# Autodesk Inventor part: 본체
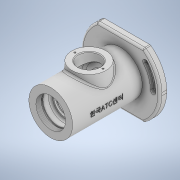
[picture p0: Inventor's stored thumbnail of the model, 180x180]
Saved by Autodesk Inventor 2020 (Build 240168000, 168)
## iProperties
Created: 2022-05
Part Number: 본체
Material: 일반
Document SubType Name: Modeling
Designer: Student
Density: 1 g/cm^3
Appearance: 기본값
Mass: 253.813 g
Surface Area: 621.423 cm^2
Volume: 253.813 cm^3
Author: Student
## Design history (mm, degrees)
sketch "스케치1"
  geometry: L1 (-33.985, -47)-(33.985, -47); L2 (57.967, -1.966)-(57.967, 1.966); L3 (33.985, 47)-(-33.985, 47); L4 (-57.967, 1.966)-(-57.967, -1.966); L5 (-57.967, -47)-(57.967, 47); L6 (57.967, -47)-(-57.967, 47); A1 r 58 centre (0, 0) between (-33.985, 47) and (-33.985, -47); A2 r 58 centre (0, 0) between (33.985, -47) and (33.985, 47); 1 further point
  constraints: 12 end point, 8 point on circle, 2 centre point, 2 midpoint, 2 parallel, 1 coincident, 1 horizontal, 1 perpendicular
  dimensions: "d0" = 94 distance between parallel lines of L1 L3; "d2" = 58 radius of A2; "d3" = 58 radius of A1; "d4" = 67.97058 distance of L1.start L1.end; "d47" = 50.9645 deg angle of L5 L2; "d48" = 50.9645 deg angle of L6 L2; "d49" = 115.93332 distance between parallel lines of L2 L4; "d50" = 57.96666 distance from line of point (0, 0) L2; "d51" = 0 distance from line of L5.end L2; "d52" = 0 distance from line of L6.start L2; "d53" = 115.93332 distance from line of L6.end L2; "d54" = 115.93332 distance from line of L5.start L2
extrude "돌출1" new body sketch "스케치1" distance "d5" = 10; taper "d6" = 0 deg
sketch "스케치2"
  geometry: C1 r 36 at (0, 0); 1 further point
  constraints: 1 centre point, 1 coincident
  dimensions: "d7" = 36 radius of C1
extrude "돌출2" join sketch "스케치2" distance "d8" = 3; taper "d9" = 0 deg
sketch "스케치3"
  geometry: C1 r 32 at (0, 0); 1 further point
  constraints: 1 centre point, 1 coincident
  dimensions: "d10" = 32 radius of C1
extrude "돌출3" join sketch "스케치3" distance "d11" = 102; taper "d12" = 0 deg
sketch "스케치4"
  geometry: L1 (0, -30.846)-(0, 129.662); L2 (32, 112)-(-32, 112) reference; L3 (22.5, 112)-(22.5, 104); L4 (22.5, 104)-(24, 104); L5 (24, 104)-(24, 101); L6 (24, 101)-(22.5, 101); L7 (22.5, 101)-(22.5, 90); L8 (22.5, 90)-(17.5, 90); L9 (17.5, 90)-(17.5, 87.75); L10 (17.5, 87.75)-(18.5, 87.75); L11 (18.5, 87.75)-(18.5, 86); L12 (18.5, 86)-(17.5, 86); L13 (17.5, 86)-(17.5, 75); L14 (17.5, 75)-(27, 75); L15 (27, 75)-(27, 37); L16 (27, 37)-(17.5, 37); L17 (17.5, 37)-(17.5, 26); L18 (17.5, 26)-(15, 26); L19 (15, 26)-(15, 21); L20 (15, 21)-(11, 21); L21 (11, 21)-(11, 18.3); L22 (11, 18.3)-(15, 18.3); L23 (-32, 10)-(32, 10) reference; L24 (-36, -3)-(36, -3) reference; L25 (20, 11)-(30, -3); L26 (15, 18.3)-(15, 11.7); L27 (15, 11.7)-(15.404, 11); L28 (15.404, 11)-(20, 11); L29 (30, -3)-(38.114, -17.054); 5 further points
  constraints: 52 end point, 16 perpendicular, 9 point on line, 3 vertical, 1 horizontal, 1 parallel
  dimensions: "d14" = 48 diameter of L5 L1; "d15" = 45 diameter of L7 L1; "d16" = 54 diameter of L15 L1; "d17" = 30 diameter of L19 L1; "d18" = 35 diameter of L9 L1; "d20" = 22 diameter of L21 L1; "d23" = 37 diameter of L11 L1; "d24" = 1.75 distance of L10.end L11.end; "d25" = 11 distance of L12.end L13.end; "d27" = 8 distance of L3.start L3.end; "d28" = 3 distance of L4.end L5.end; "d29" = 22 distance of L7.end L3.start; "d31" = 38 distance of L14.end L15.end; "d32" = 11 distance of L16.end L17.end; "d33" = 5 distance of L18.end L19.end; "d41" = 60 diameter of L25.end L1; "d42" = 40 diameter of L25.start L1; "d44" = 4 distance from line of L12.end L8; "d45" = 17.66206 distance from line of L1.end L2; "d46" = 142.84649 distance from line of L1.start L2; "d67" = 6.6 distance of L22.end L26.end; "d68" = 30 deg angle of L26 L27; "d69" = 30 diameter of L26 L1; "d70" = 0.7 vertical distance of L27.end L26.end; "d71" = 14 vertical distance of L25.end L25.start; "d109" = 129.05367 distance from line of L29.end L2; "d110" = 102 distance from line of point (20.714, 10) L2; "d111" = 0 distance from line of point (0, 112) L2; "d112" = 102 distance from line of point (0, 10) L2; "d113" = 1.54166 distance from line of point (20.714, 10) L29; "d114" = 31.51924 distance from line of point (0, 112) L29; "d115" = 19.48076 distance from line of point (0, 10) L29
revolve "회전1" sketch "스케치4" stored, may be unused: angle "d55" = 90 deg
node "작업 평면1"
sketch "스케치5"
  geometry: L1 (32, 112)-(-32, 112) reference; C1 r 25 at (0, 56); 1 further point
  constraints: 1 centre point
  dimensions: "d57" = 25 radius of C1; "d58" = 56 distance from line of L1 C1.centre; "d59" = 64.49806 distance of L1.start C1.centre
extrude "돌출4" join sketch "스케치5" stored distance "d60" = 10; taper "d61" = 5 deg
sketch "스케치6"
  geometry: L1 (33.985, 56)-(-33.985, 56) reference; C1 r 16 at (0, 0); 2 further points
  constraints: 1 centre point, 1 midpoint, 1 vertical alignment
  dimensions: "d62" = 16 radius of C1; "d63" = 56 distance of point (0, 56) C1.centre
extrude "돌출5" cut sketch "스케치6" distance "d64" = 20; taper "d65" = 0 deg
sketch "스케치7"
  geometry: L1 (-70.765, 0)-(82.559, 0); L2 (-36.77, -30.854)-(0, 0); L3 (0, 0)-(36.77, 30.854); A1 r 48 centre (0, 0) between (48, 0) and (-48, 0); A2 r 48 centre (0, 0) between (48, 0) and (36.77, 30.854); A3 r 52 centre (0, 0) between (52, 0) and (39.834, 33.425); A4 r 44 centre (0, 0) between (44, 0) and (33.706, 28.283); A5 r 4 centre (48, 0) between (44, 0) and (52, 0); A6 r 4 centre (36.77, 30.854) between (39.834, 33.425) and (33.706, 28.283); A7 r 58 centre (0, 0) between (57.967, 1.966) and (33.985, 47) reference; A8 r 48 centre (0, 0) between (-48, 0) and (-36.77, -30.854); A9 r 52 centre (0, 0) between (-52, 0) and (-39.834, -33.425); A10 r 44 centre (0, 0) between (-44, 0) and (-33.706, -28.283); A11 r 4 centre (-48, 0) between (-44, 0) and (-52, 0); A12 r 4 centre (-36.77, -30.854) between (-39.834, -33.425) and (-33.706, -28.283); A13 r 46.25 centre (0, 0) between (-46.25, 0) and (-35.43, -29.729); A14 r 1.75 centre (-48, 0) between (-46.25, 0) and (-49.75, 0); A15 r 49.75 centre (0, 0) between (-49.75, 0) and (-38.111, -31.979); A16 r 1.75 centre (-36.77, -30.854) between (-38.111, -31.979) and (-35.43, -29.729); A17 r 49.75 centre (0, 0) between (49.75, 0) and (38.111, 31.979); A18 r 1.75 centre (48, 0) between (46.25, 0) and (49.75, 0); A19 r 46.25 centre (0, 0) between (46.25, 0) and (35.43, 29.729); A20 r 1.75 centre (36.77, 30.854) between (38.111, 31.979) and (35.43, 29.729); 1 further point
  constraints: 38 point on circle, 19 centre point, 8 tangent, 6 end point, 3 coincident, 3 concentric, 1 horizontal, 6 other
  dimensions: "d66" = 48 radius of A1; "d72" = 4 radius of A6; "d73" = 4 radius of A12 (derived); "d74" = 40 deg angle of L1 L2; "d75" = 40 deg angle of L3 L1; "d76" = 1.96623 distance from line of A7.start L1; "d77" = 53.06809 distance from line of L1.end L3; "d78" = 33.42496 distance from line of A3.start L3; "d81" = 28.28265 distance from line of A10.start L3; "d82" = 45.48694 distance from line of L1.start L3; "d83" = 2.25 radial gap between concentric circles of A10 A13; "d84" = 2.25 radial gap between concentric circles of A3 A17
extrude "돌출6" cut sketch "스케치7" distance "d85" = 10; taper "d86" = 0 deg
extrude "돌출7" cut sketch "스케치7" distance "d87" = 4.4; taper "d88" = 0 deg
sketch "스케치8"
  geometry: A1 r 4 centre (-48, 0) between (-44, 0) and (-52, 0) reference; A2 r 4 centre (36.77, 30.854) between (39.834, 33.425) and (33.706, 28.283) reference; A3 r 4 centre (-36.77, -30.854) between (-39.834, -33.425) and (-33.706, -28.283) reference; 1 further point
sketch "스케치9"
  geometry: 1 further point
sketch "스케치10" dims "d96" = 20.5
  geometry: L1 (33.985, 56)-(-33.985, 56) reference; 4 further points
  constraints: 1 horizontal alignment, 1 midpoint, 1 vertical alignment, 2 other
  dimensions: "d97" = 56 distance of point (0, 56) point (0, 0); "d98" = 59.6343 distance of point (0, 56) point (-20.5, 0)
hole "구멍2" sketch "스케치10" at (-20.5, 0) diameter "d99" = 2.459; stored, may be unused: countersink angle "d103" = 90 deg, drill point angle "d105" = 118 deg; dims "d100" = 6, "d101" = 4, "d102" = 2, "d104" = 8
fillet "모깎기1" dims "d116" = 0.5
fillet "모깎기2" dims "d117" = 0.6
fillet "모깎기4" dims "d119" = 3
fillet "모깎기5" dims "d120" = 3
chamfer "모따기1" distance "d121" = 1; stored, may be unused: second distance "d122" = 2, angle "d123" = 45 deg
sketch "스케치11"
  geometry: C1 r 22.5 at (0, 0) reference; C2 r 22.5 at (0, 0); 1 further point
  constraints: 1 centre point, 1 coincident, 1 concentric
extrude "돌출8" join sketch "스케치11" distance "d124" = 8; taper "d125" = 0 deg
sketch "스케치12"
  geometry: C1 r 11 at (0, 0) reference; 1 further point
hole "구멍3" sketch "스케치12" at (0, 0) diameter "d126" = 43.376; stored, may be unused: countersink angle "d130" = 90 deg, drill point angle "d132" = 118 deg; dims "d127" = 8, "d128" = 4, "d129" = 2, "d131" = 10
node "작업 평면2"
sketch "스케치13"
  geometry: L1 (23.389, 86.887)-(23.389, 37.113); L2 (23.389, 37.113)-(-23.389, 37.113); L3 (-23.389, 37.113)-(-23.389, 86.887); L4 (-23.389, 86.887)-(23.389, 86.887); L5 (-36, -2)-(36, -2) reference; L6 (23.389, 62)-(-23.389, 62); L7 (46.4, 0)-(1.966, 0) reference; 3 further points
  constraints: 4 midpoint, 2 end point, 1 vertical alignment, 2 other
  dimensions: "d134" = 62 distance between parallel lines of L7 L6; "d135" = 86.88738 distance between parallel lines of L4 L7; "d136" = 46.77715 distance between parallel lines of L1 L3
feature "엠보싱1" sketch "스케치13" dims "d137" = 0.5, "d138" = 0
fillet "모깎기6" dims "d139" = 3
hole "구멍4" sketch "스케치8" diameter "d140" = 8; stored, may be unused: countersink angle "d144" = 90 deg, drill point angle "d146" = 0 deg; dims "d141" = 8, "d142" = 4, "d143" = 2, "d145" = 15
node "솔리드1"
pattern_circular "원형 패턴1" dims angle "d107" = 360 deg
feature "A9D066F2-1C7D-4E18-AEED-F7BC21143FA4" dims "d140" = 8, "d141" = 8, "d142" = 4, "d143" = 2, "d144" = 90 deg, "d145" = 15, "d146" = 0
other parameters: "d1" = 58, "d56" = 38, "d133" = 32
